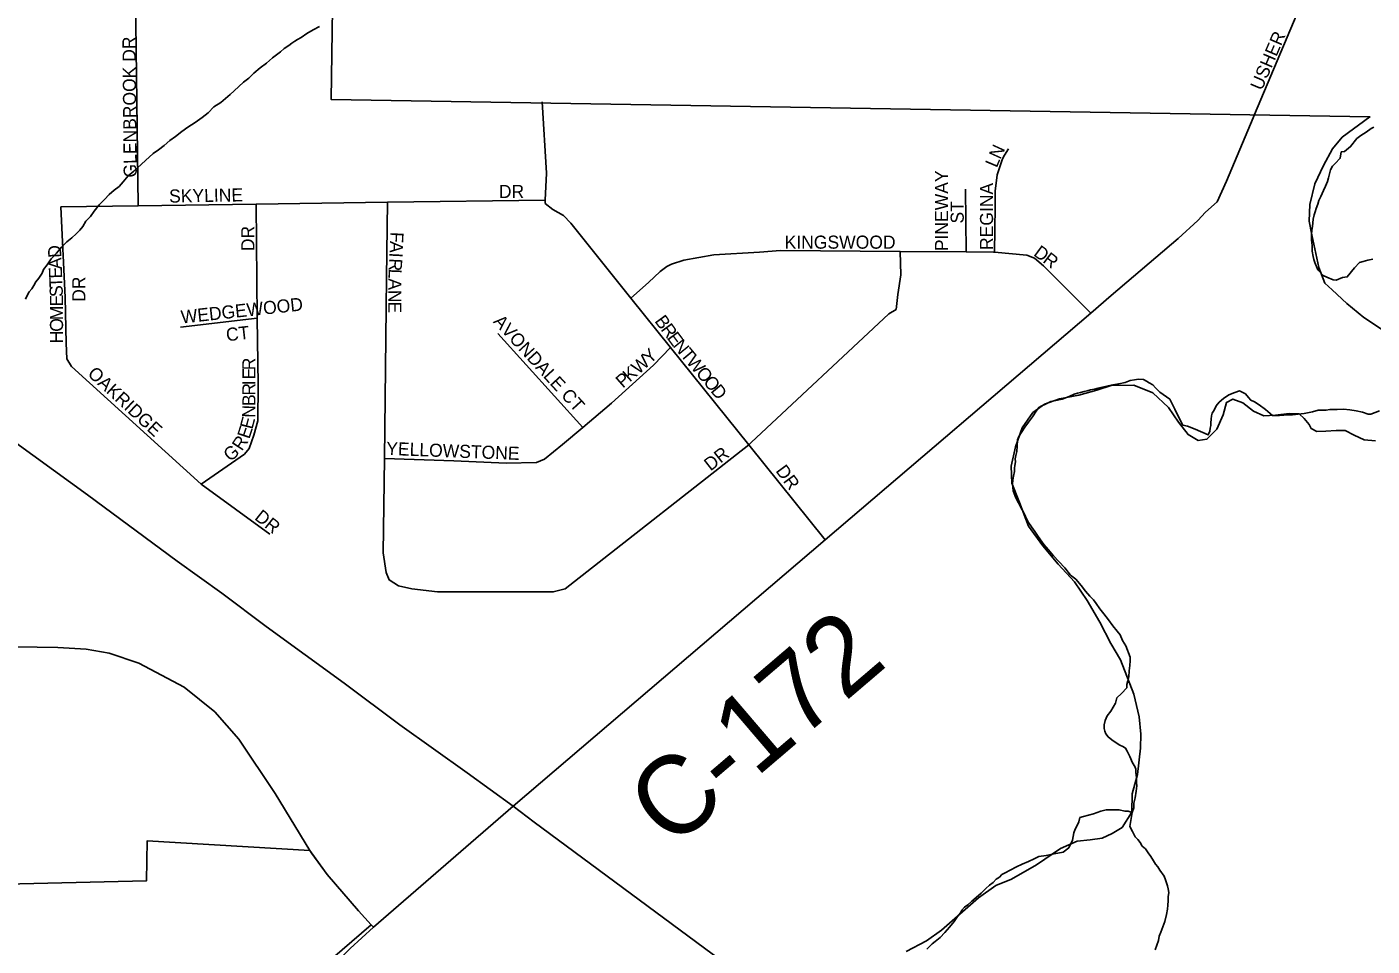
# Model space of a CAD drawing. Extents: x 2010165 to 2382125, y 1060529 to 1407316.
# Drawn here: x 2126446 to 2131582, y 1224542 to 1228053 of the extents above; entities that cross this region are included whole.
import ezdxf

# ---------------------------------------------------------------- set-up
doc = ezdxf.new("R2010")
doc.units = 0
for name, color, linetype in [('GM_X_City_Street', 7, 'Continuous'), ('GM_X_City_Street_Text', 7, 'Continuous'), ('GM_X_Corporation', 7, 'Continuous'), ('GM_X_County_Road', 7, 'Continuous'), ('GM_X_County_Road_Text', 7, 'Continuous'), ('GM_X_Interstate_Route', 7, 'Continuous'), ('GM_X_Minor_River', 7, 'Continuous'), ('GM_X_Township_Subdivision', 7, 'Continuous'), ('GM_X_Township_Subdivision_Text', 7, 'Continuous')]:
    doc.layers.add(name, color=color, linetype=linetype)

msp = doc.modelspace()

# ---------------------------------------------------------------- linework, layer by layer
at = {"layer": 'GM_X_City_Street'}
msp.add_lwpolyline([(2131133.5, 1227718.6), (2131344.2, 1228219.6), (2131737.3, 1229190.2)], dxfattribs=at)
at = {"layer": 'GM_X_Corporation'}
for points in [[(2131636.8, 1226885.6), (2131550.4, 1226943.1), (2131486.1, 1226996.8), (2131429.8, 1227048.5), (2131401.6, 1227074.4), (2131379.2, 1227134.4), (2131352.4, 1227258.4), (2131342.1, 1227310.5), (2131343.7, 1227374.6), (2131363.2, 1227453), (2131396.7, 1227523.3), (2131430.3, 1227587.7), (2131468, 1227632.1), (2131573.5, 1227709), (2127608.1, 1227775.4), (2127641.5, 1230030.5), (2127699.3, 1232671.6), (2128286.9, 1232638.9), (2128858.2, 1232617.9), (2130176.4, 1232600.5), (2130656, 1232568.1), (2130665.6, 1232672.5), (2131903.1, 1232704.3)], [(2129802.5, 1224521.6), (2129880.2, 1224562.2), (2129937.9, 1224602.7), (2130079.1, 1224726), (2130144.8, 1224772.6), (2130204.6, 1224797), (2130300.2, 1224851.8), (2130391.8, 1224914.6), (2130455.6, 1224943.1), (2130505.6, 1224947.5), (2130551.5, 1224953.8), (2130589.4, 1224972.1), (2130627.2, 1224994.4), (2130664.8, 1225052.8), (2130666.4, 1225123), (2130685.9, 1225197.3), (2130697.2, 1225297.6), (2130698.9, 1225351.7), (2130692.5, 1225417.8), (2130671.9, 1225503.8), (2130621.1, 1225635.8), (2130584.7, 1225697.7), (2130542.2, 1225779.5), (2130493.7, 1225861.4), (2130445.2, 1225933.2), (2130382.8, 1226000.9), (2130324.4, 1226070.6), (2130269.9, 1226146.4), (2130235.3, 1226236.4), (2130206.8, 1226310.4), (2130204.4, 1226374.5), (2130219.9, 1226448.7), (2130245.5, 1226521.1), (2130287.1, 1226579.5), (2130330.9, 1226611.9), (2130388.7, 1226632.3), (2130462.6, 1226646.9), (2130530.5, 1226665.4), (2130586.3, 1226683.8), (2130672.3, 1226684.4), (2130744.5, 1226654.9), (2130804.8, 1226599.2), (2130843.2, 1226543.3), (2130879.5, 1226495.5), (2130917.6, 1226473.7), (2130951.6, 1226477.9), (2130989.3, 1226516.3), (2131012.9, 1226570.6), (2131026.6, 1226618.8), (2131050.6, 1226631), (2131088.6, 1226617.2), (2131128.8, 1226585.4), (2131168.9, 1226567.6), (2131212.9, 1226570), (2131264.9, 1226576.3), (2131302.9, 1226574.6), (2131323, 1226556.7), (2131341.1, 1226534.8), (2131349.2, 1226518.8), (2131371.3, 1226506.9), (2131405.2, 1226509.2), (2131445.2, 1226511.5), (2131479.2, 1226511.7), (2131513.3, 1226493.9), (2131551.4, 1226476.1), (2131595.4, 1226472.4)], [(2125722.4, 1224498.6), (2125717.9, 1224762.7), (2126903.2, 1224791.4), (2126905.3, 1224943.3), (2127526, 1224906.7), (2127592.2, 1224815.3), (2127712, 1224676.6), (2127760.6, 1224622.5), (2127612.9, 1224495.2)]]:
    msp.add_lwpolyline(points, dxfattribs=at)
at = {"layer": 'GM_X_County_Road'}
for points in [[(2127768.8, 1224613.5), (2128302.2, 1225075.8), (2129493.2, 1226093.3), (2130507.6, 1226960), (2130586.3, 1227027.1), (2130841.6, 1227244.2), (2130916.8, 1227313.5), (2130945.5, 1227344.8), (2130989.9, 1227384.7), (2131026.7, 1227464.4), (2131128.4, 1227706.3), (2131133.5, 1227718.6)], [(2124740.5, 1225703.5), (2124749.1, 1225703.4), (2126407, 1225685.3), (2126564.6, 1225682.1), (2126671.8, 1225675.8), (2126760.1, 1225660.1), (2126873.5, 1225622.3), (2127046.9, 1225530.8), (2127163.5, 1225436.3), (2127255, 1225332.2), (2127393.6, 1225124.2), (2127526, 1224906.7), (2127534.3, 1224895.2)], [(2127534.3, 1224895.2), (2127592.2, 1224815.3), (2127712, 1224676.6), (2127760.6, 1224622.6), (2127768.8, 1224613.5)], [(2127619.8, 1224469.6), (2127620.9, 1224471.2), (2127680.3, 1224533), (2127768.8, 1224613.5)]]:
    msp.add_lwpolyline(points, dxfattribs=at)
at = {"layer": 'GM_X_Interstate_Route'}
msp.add_lwpolyline([(2123475.5, 1227509.9), (2124443.7, 1227272.2), (2124647.3, 1227222.4), (2124905.8, 1227162.1), (2125007.6, 1227137.2), (2125158.9, 1227094.4), (2125359.9, 1227026.5), (2125508.5, 1226969), (2125701.3, 1226886.4), (2125888.7, 1226792.8), (2126026.5, 1226713.5), (2126161.6, 1226630.5), (2126338.1, 1226511.3), (2126677.5, 1226265.6), (2127019.7, 1226012.5), (2127190.8, 1225889.7), (2127359.2, 1225763.1), (2127657.2, 1225546.3), (2127869.7, 1225387.2), (2128126.4, 1225203), (2128302.2, 1225075.8), (2128383, 1225015), (2129061.9, 1224512.7), (2129183.2, 1224428.9)], dxfattribs=at)
at = {"layer": 'GM_X_Minor_River'}
for points in [[(2126441.1, 1227012.6), (2126446.9, 1227026.7), (2126454.7, 1227040.8), (2126464.5, 1227053), (2126472.4, 1227065.2), (2126480.2, 1227079.3), (2126492, 1227093.6), (2126503.8, 1227111.8), (2126509.6, 1227125.9), (2126523.4, 1227144.2), (2126539.1, 1227166.5), (2126558.8, 1227188.8), (2126578.5, 1227211.2), (2126598.3, 1227231.6), (2126618.1, 1227247.9), (2126634, 1227262.2), (2126647.8, 1227276.4), (2126659.6, 1227290.7), (2126671.3, 1227310.9), (2126689.1, 1227329.2), (2126702.9, 1227349.5), (2126722.6, 1227373.8), (2126742.3, 1227394.2), (2126760.1, 1227412.5), (2126779.9, 1227428.9), (2126797.8, 1227443.2), (2126813.5, 1227461.5), (2126833.3, 1227483.8), (2126855, 1227502.2), (2126928.3, 1227569.5), (2126948.1, 1227583.8), (2126969.9, 1227600.2), (2126991.7, 1227618.6), (2127013.5, 1227635), (2127037.3, 1227653.4), (2127061.2, 1227669.8), (2127089, 1227688.2), (2127114.8, 1227706.7), (2127138.6, 1227725.1), (2127160.3, 1227747.5), (2127186.1, 1227763.9), (2127203.9, 1227780.2), (2127221.8, 1227794.5), (2127237.6, 1227808.8), (2127255.4, 1227825.1), (2127273.2, 1227841.4), (2127293, 1227857.8), (2127312.8, 1227876.1), (2127336.6, 1227896.6), (2127360.4, 1227914.9), (2127384.2, 1227935.4), (2127413.9, 1227957.9), (2127427.8, 1227970.1), (2127445.6, 1227982.4), (2127457.6, 1227990.6), (2127469.5, 1227998.8), (2127479.4, 1228005), (2127493.3, 1228013.2), (2127515.2, 1228027.6), (2127539, 1228042), (2127562.9, 1228054.4)], [(2131589, 1227669.6), (2131579, 1227665.4), (2131559.2, 1227651.1), (2131549.3, 1227644.9), (2131539.3, 1227638.8), (2131523.5, 1227626.5), (2131499.8, 1227596), (2131476, 1227577.6), (2131464, 1227575.4), (2131460.4, 1227551.3), (2131440.6, 1227530.9), (2131430.8, 1227520.8), (2131422.9, 1227506.6), (2131421.1, 1227496.6), (2131415.4, 1227476.4), (2131411.5, 1227462.3), (2131403.8, 1227444.1), (2131396, 1227428), (2131386.3, 1227405.7), (2131378.5, 1227389.6), (2131374.7, 1227375.5), (2131368.9, 1227359.3), (2131365.1, 1227347.2), (2131361.3, 1227335.1), (2131357.5, 1227319), (2131355.7, 1227305), (2131353.9, 1227290.9), (2131352.1, 1227274.8), (2131350.3, 1227260.7), (2131350.6, 1227238.7), (2131352.9, 1227218.6), (2131353.2, 1227196.6), (2131357.5, 1227176.6), (2131359.7, 1227164.6), (2131363.9, 1227152.6), (2131374.3, 1227124.6), (2131394.7, 1227102.8), (2131408.8, 1227097), (2131433, 1227087.3), (2131445.1, 1227085.5), (2131469, 1227095.9), (2131487, 1227098.2), (2131514.6, 1227132.7), (2131534.3, 1227153.1), (2131548.3, 1227157.3), (2131566.3, 1227161.5), (2131584.3, 1227165.8)], [(2131576.8, 1226573.7), (2131566.8, 1226573.6), (2131544.7, 1226581.3), (2131520.5, 1226586.9), (2131496.4, 1226590.6), (2131472.3, 1226592.3), (2131448.2, 1226591.9), (2131430.2, 1226591.6), (2131420.2, 1226591.5), (2131406.2, 1226589.3), (2131388.1, 1226589), (2131376.1, 1226588.8), (2131354.1, 1226582.5), (2131322.2, 1226576), (2131278.1, 1226571.4), (2131262.1, 1226571.1), (2131228, 1226568.6), (2131202, 1226568.2), (2131175.5, 1226591.9), (2131151.2, 1226609.7), (2131133, 1226621.4), (2131118.9, 1226627.2), (2131110.7, 1226637.2), (2131098.5, 1226651), (2131088.4, 1226656.9), (2131076.3, 1226662.7), (2131058.3, 1226656.5), (2131034.4, 1226648.1), (2131014.5, 1226633.8), (2130998.7, 1226619.5), (2130986.8, 1226605.3), (2130979.1, 1226589.1), (2130971.2, 1226576.9), (2130969.4, 1226566.9), (2130967.5, 1226554.8), (2130965.7, 1226540.7), (2130965.9, 1226530.7), (2130964, 1226520.6), (2130962.2, 1226508.6), (2130956.4, 1226494.4), (2130905.9, 1226515.8), (2130877.7, 1226527.4), (2130859.6, 1226531.1), (2130845.1, 1226559), (2130828.6, 1226592.9), (2130810, 1226630.8), (2130783.7, 1226648.4), (2130771.5, 1226658.3), (2130755.3, 1226674.1), (2130745.1, 1226686), (2130730.9, 1226693.8), (2130720.8, 1226699.7), (2130708.7, 1226705.6), (2130690.6, 1226707.3), (2130674.6, 1226705.1), (2130658.6, 1226702.8), (2130638.7, 1226694.5), (2130614.6, 1226690.1), (2130592.7, 1226685.8), (2130574.7, 1226681.5), (2130564.7, 1226679.4), (2130546.7, 1226675.1), (2130536.7, 1226672.9), (2130522.7, 1226668.7), (2130506.7, 1226666.5), (2130494.7, 1226662.3), (2130482.7, 1226660.1), (2130468.8, 1226655.9), (2130456.8, 1226653.7), (2130444.8, 1226649.5), (2130424.9, 1226641.2), (2130399, 1226630.8), (2130374.9, 1226626.4), (2130355, 1226622.1), (2130335.1, 1226611.8), (2130321.1, 1226605.6), (2130309.2, 1226599.4), (2130299.4, 1226585.2), (2130285.6, 1226562.9), (2130269.9, 1226542.6), (2130256.1, 1226524.4), (2130232.6, 1226487.9), (2130228.7, 1226475.8), (2130227.1, 1226451.7), (2130225.4, 1226431.6), (2130221.6, 1226415.5), (2130219.8, 1226403.4), (2130219.9, 1226391.4), (2130218.1, 1226377.3), (2130216.3, 1226367.3), (2130216.5, 1226355.2), (2130212.7, 1226337.1), (2130210.9, 1226321), (2130209.1, 1226306.9), (2130211.5, 1226280.9), (2130219.8, 1226260.9), (2130226.1, 1226247), (2130232.2, 1226235.1), (2130240.5, 1226217.1), (2130250.8, 1226199.2), (2130259.1, 1226183.3)], [(2131610.8, 1226586.3), (2131576.8, 1226573.7)], [(2130259.1, 1226183.3), (2130267.4, 1226163.3), (2130281.7, 1226143.5), (2130294, 1226125.6), (2130304.2, 1226109.7), (2130316.5, 1226093.8), (2130328.8, 1226075.9), (2130345.1, 1226056.1), (2130365.5, 1226032.3), (2130385.9, 1226010.5), (2130408.3, 1225986.8), (2130430.8, 1225959), (2130451, 1225943.2), (2130471.4, 1225919.5), (2130487.8, 1225897.6), (2130504.1, 1225877.8), (2130518.4, 1225864), (2130528.6, 1225850.1), (2130542.9, 1225830.2), (2130557.2, 1225810.3), (2130575.6, 1225788.5), (2130592, 1225764.7), (2130608.3, 1225744.9), (2130620.6, 1225731), (2130628.9, 1225709.1), (2130641.2, 1225689.2), (2130657.9, 1225645.2), (2130658.1, 1225631.2), (2130656.4, 1225613.1), (2130654.6, 1225593), (2130653, 1225570.9), (2130649.2, 1225554.8), (2130645.4, 1225540.7), (2130645.6, 1225528.7), (2130625.8, 1225506.3), (2130608, 1225490), (2130602.3, 1225469.9), (2130584.7, 1225439.5), (2130570.9, 1225421.2), (2130563.2, 1225403.1), (2130559.4, 1225387), (2130559.6, 1225372.9), (2130561.7, 1225362.9), (2130565.9, 1225352.9), (2130574.1, 1225341), (2130588.3, 1225329.2), (2130600.4, 1225321.3), (2130618.7, 1225309.6), (2130630.8, 1225303.7), (2130640.9, 1225297.8), (2130647.1, 1225285.9), (2130657.4, 1225266), (2130667.8, 1225242), (2130676, 1225228.1), (2130680.1, 1225218.1), (2130680.3, 1225206.1), (2130682.6, 1225184.1), (2130682.9, 1225166), (2130683.1, 1225154), (2130681.4, 1225133.9), (2130677.7, 1225107.7), (2130672, 1225087.6), (2130672.3, 1225069.5), (2130666.5, 1225051.4), (2130650.4, 1225057.2), (2130638.4, 1225057), (2130616.2, 1225062.7), (2130598.2, 1225062.4), (2130580.1, 1225062.2), (2130566.1, 1225061.9), (2130546.1, 1225057.7), (2130518.2, 1225047.2), (2130480.2, 1225036.6), (2130466.3, 1225032.4), (2130462.5, 1225016.3), (2130454.7, 1225000.1), (2130448.9, 1224988), (2130443.1, 1224973.9), (2130437.5, 1224945.7), (2130423.8, 1224917.4), (2130402, 1224901), (2130368, 1224894.5), (2130338, 1224888.1), (2130310, 1224883.6), (2130292.1, 1224875.4), (2130270.2, 1224865), (2130246.3, 1224854.6), (2130224.4, 1224844.3), (2130200.5, 1224831.9), (2130180.6, 1224821.6), (2130168.6, 1224815.4), (2130158.8, 1224805.2), (2130146.8, 1224797), (2130135, 1224784.8), (2130121.1, 1224774.5), (2130107.2, 1224762.3), (2130089.5, 1224744), (2130069.7, 1224727.6), (2130053.8, 1224713.3), (2130038, 1224699.1), (2130026.1, 1224690.9)], [(2130666.5, 1225051.4), (2130657.3, 1224999.1), (2130667.6, 1224979.2), (2130677.9, 1224959.2), (2130688.1, 1224949.4), (2130696.2, 1224937.4), (2130704.5, 1224923.5), (2130716.7, 1224913.6), (2130726.9, 1224897.8), (2130737.1, 1224883.8), (2130747.4, 1224867.9), (2130755.6, 1224854), (2130763.8, 1224844.1), (2130772, 1224832.2), (2130788.4, 1224808.3), (2130792.6, 1224794.3), (2130800.9, 1224772.4), (2130803.1, 1224760.4), (2130805.3, 1224746.4), (2130803.5, 1224730.3), (2130803.8, 1224714.2), (2130802, 1224698.2), (2130800.2, 1224682.1), (2130796.5, 1224662), (2130790.9, 1224635.8), (2130775.4, 1224595.4), (2130769.6, 1224579.3), (2130765.9, 1224563.2), (2130760.1, 1224545), (2130754.3, 1224526.9)], [(2130026.1, 1224690.9), (2130016.2, 1224678.7), (2130010.4, 1224668.6), (2129998.5, 1224654.3), (2129986.8, 1224636.1), (2129969, 1224613.8), (2129951.3, 1224593.5), (2129933.5, 1224575.1), (2129913.7, 1224558.8), (2129901.8, 1224550.6), (2129882, 1224530.2)]]:
    msp.add_lwpolyline(points, dxfattribs=at)
at = {"layer": 'GM_X_Township_Subdivision'}
for points in [[(2126870.8, 1227369.4), (2126848.1, 1229163.7)], [(2129493.2, 1226093.3), (2129201.9, 1226456.6), (2128903.6, 1226828.8), (2128752.5, 1227017.3), (2128523.3, 1227303.1), (2128494.3, 1227332.1), (2128453.7, 1227355.4), (2128424.6, 1227378.6), (2128425.3, 1227391.8), (2128430.5, 1227494.7), (2128413.2, 1227767.3)], [(2130140.2, 1227192.2), (2130143.1, 1227365.1), (2130143.2, 1227425.4), (2130150.5, 1227487.7), (2130171.2, 1227548.6), (2130178.5, 1227563.3), (2130193.4, 1227587)], [(2130032, 1227193.3), (2130029.8, 1227433)], [(2126575.3, 1227365.2), (2126870.8, 1227369.4), (2127321.2, 1227375.9), (2127822.7, 1227383.1), (2128425.3, 1227391.8)], [(2126616.3, 1226756), (2126598.7, 1226785.2), (2126595.6, 1226845.2), (2126592.7, 1227019.8), (2126575.3, 1227365.2)], [(2127112.1, 1226306.3), (2127243.5, 1226397.6), (2127276.3, 1226421.4), (2127295.3, 1226442.5), (2127312.6, 1226493.6), (2127327.9, 1226548.6), (2127328.7, 1226687.2), (2127325.9, 1226940.2), (2127321.2, 1227375.9)], [(2127822.7, 1227383.1), (2127818.6, 1227095), (2127810.9, 1226403.7), (2127806.9, 1226043.9), (2127818.4, 1225969.3), (2127829.8, 1225940.5), (2127864.3, 1225917.5), (2127915.9, 1225906), (2128013.6, 1225894.5), (2128455.8, 1225894.4), (2128501.7, 1225905.8), (2128536.3, 1225934.6), (2129201.9, 1226456.6), (2129210.5, 1226464.5), (2129211.8, 1226465.8)], [(2130507.6, 1226960), (2130368.1, 1227099.6), (2130327.5, 1227140.3), (2130292.7, 1227169.3), (2130263.7, 1227180.9), (2130140.2, 1227192.2), (2130136.1, 1227192.6), (2130032, 1227193.3), (2129780.3, 1227195.2), (2129323.8, 1227198.6), (2129242.6, 1227192.8), (2129069.3, 1227182.1), (2128953.8, 1227161.4), (2128907.1, 1227146.7), (2128889.7, 1227137.4), (2128864.3, 1227119.3), (2128819.1, 1227076.8), (2128752.5, 1227017.3)], [(2129211.8, 1226465.8), (2129736.8, 1226956.6), (2129765.5, 1226973.9), (2129771.3, 1227031.2), (2129782.8, 1227106), (2129780.3, 1227195.2)], [(2127033, 1226906.5), (2127325.9, 1226940.2)], [(2128568.4, 1226523.1), (2128243.8, 1226882.2)], [(2127810.9, 1226403.7), (2128076.6, 1226395.3), (2128275.4, 1226385.9), (2128391.8, 1226389.1), (2128422.8, 1226401.7), (2128490.5, 1226457.2), (2128568.4, 1226523.1), (2128678.1, 1226616), (2128838.9, 1226761), (2128903.6, 1226828.8)], [(2126616.3, 1226756), (2127112.1, 1226306.3), (2127374.2, 1226115.4)]]:
    msp.add_lwpolyline(points, dxfattribs=at)

# ---------------------------------------------------------------- texts
at = {"layer": 'GM_X_City_Street_Text'}
msp.add_text('USHER', height=50, rotation=66.8017, dxfattribs=at).set_placement((2131160.9, 1227807.3))
at = {"layer": 'GM_X_County_Road_Text'}
msp.add_text('C-172', height=300, rotation=40.5111, dxfattribs=at).set_placement((2128907.7, 1224908.1))
at = {"layer": 'GM_X_Township_Subdivision_Text'}
for s, rotation, p in [('GLENBROOK DR', 90.5302, (2126865.7, 1227477.9)), ('N', 65.5759, (2130162.4, 1227544.4)), ('L', 67.0292, (2130148.8, 1227512.3)), ('PINEWAY', 90, (2129963.3, 1227196.4)), ('REGINA', 90, (2130134.9, 1227200.8)), ('SKYLINE', 0.9705, (2126989.4, 1227381.8)), ('DR', 0, (2128247.9, 1227399.4)), ('ST', 90, (2130022.9, 1227302)), ('DR', 90, (2127314.5, 1227196.4)), ('F', 267.158, (2127834.7, 1227270.7)), ('KINGSWOOD', 0, (2129339.1, 1227205.8)), ('D', 92.3433, (2126577.9, 1227172.1)), ('A', 267.1611, (2127833, 1227235.5)), ('D', 323.7509, (2130286.2, 1227182)), ('A', 92.3372, (2126579.7, 1227128.1)), ('R', 267.1535, (2127829.7, 1227169.6)), ('I', 267.1572, (2127830.8, 1227191.6)), ('R', 322.5691, (2130321.5, 1227156.2)), ('E', 92.3344, (2126581.2, 1227092.9)), ('T', 92.3153, (2126582.6, 1227057.8)), ('DR', 90, (2126669.2, 1227002.8)), ('A', 269.5536, (2127826.3, 1227092.6)), ('L', 267.6926, (2127827.7, 1227129.6)), ('S', 91.9081, (2126583.8, 1227022.2)), ('N', 270.0096, (2127825.9, 1227048.2)), ('E', 90.466, (2126584.1, 1226985.6)), ('WEDGEWOOD', 6.2048, (2127036.9, 1226919.7)), ('E', 270, (2127826, 1227004.2)), ('M', 90.0114, (2126584.1, 1226932.4)), ('AVONDALE CT', 312.5095, (2128224.1, 1226925.6)), ('B', 306.0684, (2128840.7, 1226929.1)), ('O', 90.0109, (2126584.1, 1226888.4)), ('H', 90.0219, (2126584.1, 1226844.4)), ('CT', 6.3369, (2127209.2, 1226851.9)), ('R', 306.079, (2128864, 1226897.1)), ('E', 306.5872, (2128887.7, 1226864.7)), ('N', 309.1212, (2128910.1, 1226834.5)), ('R', 90, (2127318.9, 1226741.4)), ('W', 41.56, (2128780.9, 1226723.5)), ('Y', 44.0821, (2128825.4, 1226763)), ('T', 309.9093, (2128938.4, 1226799.8)), ('W', 309.9231, (2128961, 1226772.8)), ('OAKRIDGE', 317.2456, (2126674.7, 1226723.7)), ('E', 90, (2127318.9, 1226706.2)), ('K', 41.3789, (2128747.7, 1226694.3)), ('O', 309.9265, (2128997.7, 1226728.9)), ('I', 90, (2127318.9, 1226684.2)), ('R', 90, (2127318.9, 1226644.6)), ('P', 41.3749, (2128721.3, 1226671)), ('O', 309.9315, (2129025.9, 1226695.2)), ('D', 309.9091, (2129054.1, 1226661.4)), ('B', 90.0357, (2127318.9, 1226605)), ('N', 88.2757, (2127317.6, 1226559.4)), ('E', 71.9331, (2127295.3, 1226476.5)), ('E', 75.6378, (2127307.2, 1226513.4)), ('R', 56.5948, (2127267.1, 1226430.3)), ('G', 39.1479, (2127221.9, 1226390.2)), ('YELLOWSTONE', 357.7976, (2127817.4, 1226418.2)), ('DR', 38.1517, (2129056.2, 1226354.4)), ('DR', 306.2542, (2129302.7, 1226357.1)), ('DR', 321.3402, (2127312.2, 1226174.1))]:
    msp.add_text(s, height=50, rotation=rotation, dxfattribs=at).set_placement(p)

doc.saveas('drawing.dxf')
